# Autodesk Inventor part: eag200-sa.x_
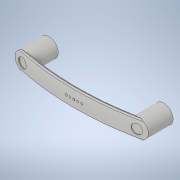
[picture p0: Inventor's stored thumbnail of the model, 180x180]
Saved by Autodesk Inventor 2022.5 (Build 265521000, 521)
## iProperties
Created: 2021-08
Part Number: eag200-sa.x_
Material: 一般
Document SubType Name: Modeling
Designer: ImaoCorp
Density: 1 g/cm^3
Appearance: 既定
Sending System: SOLIDWORKS 2019-2019304
MC: AMD64
MC_MODEL: Intel64 Family 6 Model 60 Stepping 3, GenuineIntel
OS: Windows_NT
FRU: Parasolid Version 31.0, build 290,  9- 1-2019
FORMAT: text
GUISE: transmit
KEY: eag200-sa
FILE: eag200-sa.x_t
DATE: Wed Aug 11 15:04:02 2021
Author: ImaoCorp
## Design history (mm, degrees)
feature "Base1"
node "ソリッド1"
